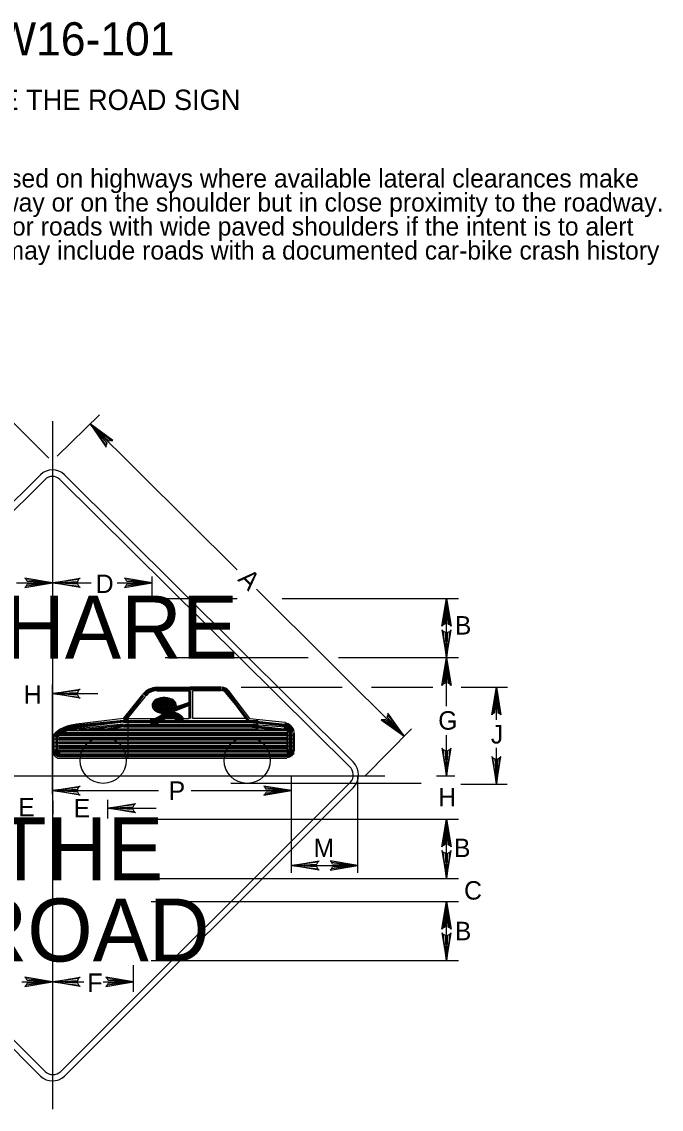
# Model space of a CAD drawing. Extents: x 0.012 to 0.188, y 0.004 to 0.259.
# Drawn here: x 0.1016 to 0.1882, y 0.112 to 0.2592 of the extents above; entities that cross this region are included whole.
import ezdxf

# ---------------------------------------------------------------- set-up
doc = ezdxf.new("R2010")
doc.units = 0
for name, color, linetype in [('1', 7, 'Continuous'), ('12', 7, 'Continuous'), ('2', 7, 'Continuous'), ('3', 7, 'Continuous')]:
    doc.layers.add(name, color=color, linetype=linetype)

# ---------------------------------------------------------------- blocks, each defined once
blk = doc.blocks.new('RARROW')
at = {"layer": '3'}
for p, q in [((-2.156, 0.28500000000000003), (-2.2665, 0.384625)), ((-2.2665, 0.384625), (0, 0)), ((0, 0), (-2.2665, -0.379125)), ((-2.156, 0.28500000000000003), (-2.075625, 0.12075)), ((0, 0), (-2.156, 0.28500000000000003)), ((-2.14975, -0.2705), (0, 0)), ((-2.075625, 0.12075), (0, 0)), ((0, 0), (-2.074, -0.108)), ((-2.2665, -0.379125), (-2.14975, -0.2705)), ((-2.074, -0.108), (-2.14975, -0.2705))]:
    blk.add_line(p, q, dxfattribs=at)

msp = doc.modelspace()

# ---------------------------------------------------------------- linework, layer by layer
at = {"layer": '1'}
for p, q in [((0.099875, 0.20550000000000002), (0.10525, 0.200125)), ((0.10575, 0.205125), (0.10575, 0.112)), ((0.106375, 0.200375), (0.112125, 0.20600000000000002)), ((0.110875, 0.20475000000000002), (0.13075, 0.185)), ((0.133375, 0.182375), (0.153375, 0.1625)), ((0.136875, 0.181125), (0.16075, 0.181125)), ((0.15912500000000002, 0.173125), (0.15912500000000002, 0.181125)), ((0.121, 0.173125), (0.140375, 0.173125)), ((0.1445, 0.173125), (0.16075, 0.173125)), ((0.15912500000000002, 0.16653560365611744), (0.15912500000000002, 0.173125)), ((0.13129158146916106, 0.16912213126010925), (0.14500189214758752, 0.16912213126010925)), ((0.14898049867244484, 0.16912213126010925), (0.15729158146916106, 0.16912213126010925)), ((0.161125, 0.169125), (0.167375, 0.169125)), ((0.165875, 0.16472308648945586), (0.165875, 0.169125)), ((0.148125, 0.15712500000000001), (0.154375, 0.1635)), ((0.1591348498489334, 0.15728102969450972), (0.1591348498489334, 0.1626118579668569)), ((0.165875, 0.156), (0.165875, 0.16091147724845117)), ((0.06075, 0.15712500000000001), (0.15075, 0.15712500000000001)), ((0.12991658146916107, 0.15612213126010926), (0.15570406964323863, 0.15612213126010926)), ((0.147125, 0.14400000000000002), (0.147125, 0.15712500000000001)), ((0.15775, 0.15712500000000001), (0.16025, 0.15712500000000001)), ((0.15916658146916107, 0.15712213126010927), (0.15916658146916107, 0.15712213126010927)), ((0.16105566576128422, 0.15602134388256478), (0.16733199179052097, 0.15602134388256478)), ((0.115625, 0.15125), (0.16075, 0.15125)), ((0.15912500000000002, 0.14325000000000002), (0.15912500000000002, 0.15125)), ((0.15916658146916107, 0.15124713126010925), (0.15916658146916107, 0.15124713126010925)), ((0.138125, 0.145), (0.147125, 0.145)), ((0.115625, 0.14325000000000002), (0.16075, 0.14325000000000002)), ((0.11912500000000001, 0.140125), (0.16075, 0.140125)), ((0.15912500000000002, 0.132125), (0.15912500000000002, 0.140125)), ((0.11912500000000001, 0.132125), (0.16075, 0.132125))]:
    msp.add_line(p, q, dxfattribs=at)
at = {"layer": '12'}
for p, q in [((0.065, 0.159), (0.104125, 0.197875)), ((0.065625, 0.15837500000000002), (0.10475, 0.19725)), ((0.10675, 0.19725), (0.146, 0.15837500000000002)), ((0.107375, 0.197875), (0.1465, 0.159)), ((0.11925000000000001, 0.1815), (0.11925000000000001, 0.184125)), ((0.100875, 0.18325), (0.10575, 0.18325)), ((0.10575, 0.18325), (0.111, 0.18325)), ((0.1145, 0.18325), (0.11925000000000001, 0.18325)), ((0.121, 0.181125), (0.13075, 0.181125)), ((0.10575, 0.154625), (0.10575, 0.1695)), ((0.10575, 0.16825), (0.11191756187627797, 0.16825)), ((0.115375, 0.164875), (0.11800000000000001, 0.168125)), ((0.115375, 0.164625), (0.11812500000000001, 0.168)), ((0.115625, 0.164625), (0.11812500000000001, 0.168)), ((0.115625, 0.1645), (0.11837500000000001, 0.167875)), ((0.115625, 0.1645), (0.11837500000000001, 0.167875)), ((0.115875, 0.164875), (0.11837500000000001, 0.167875)), ((0.11987500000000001, 0.169125), (0.124375, 0.169125)), ((0.11987500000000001, 0.169), (0.124375, 0.169)), ((0.11987500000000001, 0.168875), (0.124375, 0.168875)), ((0.11987500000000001, 0.16875), (0.124375, 0.16875)), ((0.11987500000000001, 0.168625), (0.12425, 0.168625)), ((0.12425, 0.164875), (0.12425, 0.168625)), ((0.128625, 0.169125), (0.124375, 0.169125)), ((0.128625, 0.169), (0.124375, 0.169)), ((0.128625, 0.168875), (0.124375, 0.168875)), ((0.128625, 0.16875), (0.124375, 0.16875)), ((0.124375, 0.164875), (0.124375, 0.168625)), ((0.1245, 0.164875), (0.1245, 0.168625)), ((0.1245, 0.164875), (0.1245, 0.168625)), ((0.128625, 0.168625), (0.12475, 0.168625)), ((0.12475, 0.164875), (0.12475, 0.168625)), ((0.132125, 0.164875), (0.12925, 0.168375)), ((0.132375, 0.164625), (0.129375, 0.1685)), ((0.13225, 0.1645), (0.129375, 0.168375)), ((0.132375, 0.164625), (0.1295, 0.1685)), ((0.1325, 0.164875), (0.129625, 0.168625)), ((0.124375, 0.167), (0.1205, 0.165625)), ((0.124125, 0.167), (0.1205, 0.16575)), ((0.1205, 0.166375), (0.1225, 0.167)), ((0.1205, 0.16625), (0.1225, 0.166875)), ((0.1205, 0.166125), (0.1225, 0.16675)), ((0.120625, 0.166125), (0.122375, 0.166625)), ((0.12075, 0.166), (0.12425, 0.167)), ((0.12425, 0.166875), (0.12125, 0.16575)), ((0.12425, 0.16675), (0.1215, 0.16575)), ((0.12425, 0.166625), (0.122, 0.16575)), ((0.12425, 0.167), (0.12425, 0.166625)), ((0.115375, 0.164875), (0.109, 0.164125)), ((0.115375, 0.164875), (0.115375, 0.164875)), ((0.115875, 0.164875), (0.12425, 0.164875)), ((0.116, 0.1595), (0.116, 0.164875)), ((0.132125, 0.164875), (0.12475, 0.164875)), ((0.1325, 0.164875), (0.1325, 0.164875)), ((0.1325, 0.164875), (0.13725, 0.164375)), ((0.115375, 0.164625), (0.109, 0.164)), ((0.115375, 0.1645), (0.109, 0.163875)), ((0.115375, 0.164375), (0.109, 0.16375)), ((0.115375, 0.164375), (0.109, 0.163625)), ((0.115375, 0.164125), (0.109, 0.1635)), ((0.109375, 0.1635), (0.133625, 0.1635)), ((0.1095, 0.164125), (0.1095, 0.164125)), ((0.115375, 0.164), (0.11075, 0.1635)), ((0.115375, 0.164), (0.111875, 0.1635)), ((0.115375, 0.163875), (0.11325, 0.1635)), ((0.115375, 0.16375), (0.114, 0.1635)), ((0.115375, 0.164625), (0.133625, 0.164625)), ((0.115375, 0.1645), (0.133625, 0.1645)), ((0.115375, 0.164375), (0.133625, 0.164375)), ((0.115375, 0.164375), (0.133625, 0.164375)), ((0.115375, 0.164), (0.133625, 0.164)), ((0.115375, 0.163875), (0.133625, 0.163875)), ((0.115375, 0.163875), (0.133625, 0.163875)), ((0.115375, 0.16375), (0.133625, 0.16375)), ((0.1155, 0.164125), (0.133625, 0.164125)), ((0.132375, 0.164), (0.137, 0.163375)), ((0.132375, 0.163875), (0.137, 0.163375)), ((0.132375, 0.16375), (0.137, 0.16325)), ((0.1325, 0.164625), (0.13725, 0.164125)), ((0.1325, 0.1645), (0.13725, 0.164)), ((0.1325, 0.164375), (0.13725, 0.163875)), ((0.1325, 0.164375), (0.13725, 0.163875)), ((0.1325, 0.164125), (0.13725, 0.16375)), ((0.1325, 0.164), (0.137125, 0.1635)), ((0.10575, 0.162625), (0.1385, 0.162625)), ((0.10575, 0.1605), (0.10575, 0.162625)), ((0.10575, 0.162125), (0.1385, 0.162125)), ((0.105875, 0.1605), (0.105875, 0.162625)), ((0.106, 0.1605), (0.106, 0.162625)), ((0.106, 0.1605), (0.106, 0.162625)), ((0.10625, 0.1605), (0.10625, 0.162625)), ((0.106375, 0.1605), (0.106375, 0.162625)), ((0.1065, 0.1605), (0.1065, 0.162625)), ((0.1065, 0.1605), (0.1065, 0.162625)), ((0.106625, 0.162875), (0.1375, 0.162875)), ((0.106625, 0.162875), (0.1375, 0.162875)), ((0.106625, 0.16275), (0.1375, 0.16275)), ((0.106625, 0.162625), (0.1375, 0.162625)), ((0.106625, 0.162375), (0.1375, 0.162375)), ((0.106625, 0.162375), (0.1375, 0.162375)), ((0.106625, 0.16225), (0.1375, 0.16225)), ((0.106625, 0.162125), (0.1375, 0.162125)), ((0.106625, 0.162), (0.1375, 0.162)), ((0.106625, 0.162), (0.1375, 0.162)), ((0.107, 0.163), (0.1375, 0.163)), ((0.107125, 0.16325), (0.1375, 0.16325)), ((0.10825, 0.163375), (0.1375, 0.163375)), ((0.108625, 0.163375), (0.1375, 0.163375)), ((0.1375, 0.163), (0.1375, 0.1605)), ((0.137625, 0.163), (0.137625, 0.1605)), ((0.137625, 0.163), (0.137625, 0.1605)), ((0.137875, 0.163), (0.137875, 0.1605)), ((0.138, 0.163), (0.138, 0.1605)), ((0.138125, 0.163), (0.138125, 0.1605)), ((0.138125, 0.163), (0.138125, 0.1605)), ((0.138375, 0.163), (0.138375, 0.1605)), ((0.1385, 0.163), (0.1385, 0.1605)), ((0.10575, 0.161625), (0.1385, 0.161625)), ((0.10575, 0.161125), (0.1385, 0.161125)), ((0.10575, 0.160625), (0.1385, 0.160625)), ((0.106625, 0.16175), (0.1375, 0.16175)), ((0.106625, 0.161625), (0.1375, 0.161625)), ((0.106625, 0.1615), (0.1375, 0.1615)), ((0.106625, 0.1615), (0.1375, 0.1615)), ((0.106625, 0.16125), (0.1375, 0.16125)), ((0.106625, 0.161125), (0.1375, 0.161125)), ((0.106625, 0.161), (0.1375, 0.161)), ((0.106625, 0.161), (0.1375, 0.161)), ((0.106625, 0.160875), (0.1375, 0.160875)), ((0.106625, 0.160625), (0.1375, 0.160625)), ((0.106625, 0.1605), (0.1375, 0.1605)), ((0.106625, 0.1605), (0.1375, 0.1605)), ((0.10575, 0.160125), (0.1385, 0.160125)), ((0.106625, 0.160375), (0.1375, 0.160375)), ((0.106625, 0.160125), (0.1375, 0.160125)), ((0.106625, 0.16), (0.1375, 0.16)), ((0.106625, 0.16), (0.1375, 0.16)), ((0.106625, 0.15987500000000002), (0.1375, 0.15987500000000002)), ((0.106625, 0.15975), (0.1375, 0.15975)), ((0.106625, 0.1595), (0.1375, 0.1595)), ((0.106875, 0.1595), (0.13725, 0.1595)), ((0.113, 0.1595), (0.113, 0.1595)), ((0.10475, 0.117125), (0.065625, 0.156125)), ((0.146125, 0.15625), (0.106875, 0.117125)), ((0.138125, 0.14400000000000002), (0.138125, 0.15712500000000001)), ((0.104125, 0.1165), (0.065, 0.1555)), ((0.10575, 0.155125), (0.1201182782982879, 0.155125)), ((0.1465, 0.1555), (0.107375, 0.1165)), ((0.12456088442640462, 0.155125), (0.138125, 0.155125)), ((0.10579158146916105, 0.15373556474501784), (0.10579158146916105, 0.15188725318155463)), ((0.11325, 0.151375), (0.11325, 0.153875)), ((0.11325, 0.15275), (0.11979435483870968, 0.15275)), ((0.11675, 0.12787500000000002), (0.11675, 0.1315)), ((0.10162500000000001, 0.12925), (0.10575, 0.12925)), ((0.10575, 0.12925), (0.11, 0.12925)), ((0.112625, 0.12925), (0.11675, 0.12925))]:
    msp.add_line(p, q, dxfattribs=at)
for centre in [(0.11263112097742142, 0.15923203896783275), (0.1321283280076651, 0.15923203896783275)]:
    msp.add_circle(centre, 0.0031246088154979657, dxfattribs=at)
for centre, radius, start, end in [((0.10574999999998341, 0.19625000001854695), 0.0022980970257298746, 45, 135), ((0.1057499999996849, 0.19624999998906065), 0.0014142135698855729, 45, 135), ((0.1199205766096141, 0.16670678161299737), 0.0023998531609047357, 90, 142.46745), ((0.1199205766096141, 0.16670678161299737), 0.002279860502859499, 90, 142.46745), ((0.1199205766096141, 0.16670678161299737), 0.002159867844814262, 90, 142.46745), ((0.1199205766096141, 0.16670678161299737), 0.002039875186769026, 90, 142.46745), ((0.1199205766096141, 0.16670678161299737), 0.0019496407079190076, 90, 142.46745), ((0.12866517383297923, 0.16792870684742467), 0.0007278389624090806, 37.53137777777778, 90), ((0.12867957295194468, 0.16790670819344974), 0.0011999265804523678, 37.53137777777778, 90), ((0.12867957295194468, 0.16790670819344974), 0.001079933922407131, 37.53137777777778, 90), ((0.12867957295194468, 0.16790670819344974), 0.0009599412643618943, 37.53137777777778, 90), ((0.12867957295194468, 0.16790670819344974), 0.0008399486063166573, 37.53137777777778, 90), ((0.11889765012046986, 0.16722611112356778), 0.0024427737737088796, 272.29644444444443, 318.79271944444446), ((0.11889765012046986, 0.16722611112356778), 0.0025627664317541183, 272.29644444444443, 318.79271944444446), ((0.11889765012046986, 0.16722611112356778), 0.0026827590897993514, 272.29644444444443, 318.79271944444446), ((0.11889765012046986, 0.16722611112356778), 0.0028027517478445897, 272.29644444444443, 318.79271944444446), ((0.11889765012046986, 0.16722611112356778), 0.0029227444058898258, 272.29644444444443, 318.79271944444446), ((0.11889765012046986, 0.16722611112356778), 0.003042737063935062, 272.29644444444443, 318.79271944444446), ((0.11889765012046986, 0.16722611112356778), 0.003162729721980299, 272.29644444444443, 318.79271944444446), ((0.12165017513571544, 0.16339083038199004), 0.0024066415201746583, 35.41012500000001, 112.33950555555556), ((0.12165017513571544, 0.16339083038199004), 0.0022866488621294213, 35.41012500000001, 112.33950555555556), ((0.12165017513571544, 0.16339083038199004), 0.0021666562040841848, 35.41012500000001, 112.33950555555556), ((0.12165017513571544, 0.16339083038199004), 0.002046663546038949, 35.41012500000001, 112.33950555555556), ((0.12165017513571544, 0.16339083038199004), 0.0019266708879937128, 35.41012500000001, 112.33950555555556), ((0.12165017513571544, 0.16339083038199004), 0.0018066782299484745, 35.41012500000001, 112.33950555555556), ((0.12165017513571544, 0.16339083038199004), 0.0016866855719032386, 35.41012500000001, 112.33950555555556), ((0.12165017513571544, 0.16339083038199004), 0.0015666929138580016, 35.41012500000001, 112.33950555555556), ((0.13703152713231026, 0.16280642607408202), 0.0006616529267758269, 11.546911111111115, 82.31175555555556), ((0.13703152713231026, 0.16280642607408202), 0.0007816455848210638, 11.546911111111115, 82.31175555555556), ((0.13703152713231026, 0.16280642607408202), 0.0009016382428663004, 11.546911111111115, 82.31175555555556), ((0.13703152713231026, 0.16280642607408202), 0.0010216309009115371, 11.546911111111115, 82.31175555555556), ((0.13703152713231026, 0.16280642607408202), 0.0011416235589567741, 11.546911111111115, 82.31175555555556), ((0.13703152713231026, 0.16280642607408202), 0.001261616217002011, 11.546911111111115, 82.31175555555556), ((0.13703152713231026, 0.16280642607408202), 0.0013816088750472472, 11.546911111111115, 82.31175555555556), ((0.13703152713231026, 0.16280642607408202), 0.0015016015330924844, 11.546911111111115, 82.31175555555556), ((0.10674439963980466, 0.16043749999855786), 0.0009395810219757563, 176.185925, 266.185925), ((0.10677353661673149, 0.1605671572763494), 0.0008399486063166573, 180, 270), ((0.10677353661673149, 0.1605671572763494), 0.0007199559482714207, 180, 270), ((0.10677353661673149, 0.1605671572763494), 0.0005999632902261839, 180, 270), ((0.10677353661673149, 0.1605671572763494), 0.00047997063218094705, 180, 270), ((0.10677353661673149, 0.1605671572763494), 0.00035997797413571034, 180, 270), ((0.10677353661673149, 0.1605671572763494), 0.00023998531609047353, 180, 270), ((0.10677353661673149, 0.1605671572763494), 0.00011999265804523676, 180, 270), ((0.137542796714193, 0.1605671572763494), 0.0009599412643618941, 270, 0), ((0.137542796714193, 0.1605671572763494), 0.0008399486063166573, 270, 0), ((0.137542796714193, 0.1605671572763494), 0.0007199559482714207, 270, 0), ((0.137542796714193, 0.1605671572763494), 0.0005999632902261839, 270, 0), ((0.137542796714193, 0.1605671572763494), 0.00047997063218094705, 270, 0), ((0.137542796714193, 0.1605671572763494), 0.00035997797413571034, 270, 0), ((0.137542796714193, 0.1605671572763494), 0.00023998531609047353, 270, 0), ((0.137542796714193, 0.1605671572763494), 0.00011999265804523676, 270, 0), ((0.14474999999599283, 0.15724999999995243), 0.0024748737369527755, 315, 45), ((0.144999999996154, 0.15725000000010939), 0.0015051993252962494, 318.3664611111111, 48.366461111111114), ((0.10575000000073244, 0.11812500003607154), 0.002298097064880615, 225, 315), ((0.10581249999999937, 0.11818750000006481), 0.0015026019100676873, 225, 315)]:
    msp.add_arc(centre, radius, start, end, dxfattribs=at)
for centre, major_axis, ratio, start_param, end_param in [((0.12089701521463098, 0.16664918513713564), (-0.0016503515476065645, 4.884683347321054e-05), 0.6562755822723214, 3.1209935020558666, 7.708520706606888), ((0.12089701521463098, 0.16664918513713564), (-0.001530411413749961, 4.529686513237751e-05), 0.6293374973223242, 3.1209935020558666, 7.708520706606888), ((0.12089701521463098, 0.16664918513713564), (-0.0014104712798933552, 4.174689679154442e-05), 0.5978180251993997, 3.1209935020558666, 7.708520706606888), ((0.12089701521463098, 0.16664918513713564), (-0.0012905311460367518, 3.81969284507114e-05), 0.5604398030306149, 3.1209935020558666, 7.708520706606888), ((0.12089701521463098, 0.16664918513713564), (-0.0011705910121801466, 3.464696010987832e-05), 0.5154019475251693, 3.1209935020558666, 7.708520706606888), ((0.12089701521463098, 0.16664918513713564), (-0.0010506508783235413, 3.109699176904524e-05), 0.46008123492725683, 3.1209935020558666, 7.708520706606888), ((0.12089701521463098, 0.16664918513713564), (-0.000930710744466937, 2.7547023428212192e-05), 0.3905022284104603, 3.1209935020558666, 7.708520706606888), ((0.12089701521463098, 0.16664918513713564), (-0.0008107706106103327, 2.399705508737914e-05), 0.30033709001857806, 3.1209935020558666, 7.708520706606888), ((0.12089701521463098, 0.16664918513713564), (-0.0006908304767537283, 2.044708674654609e-05), 0.17886349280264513, 3.1209935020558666, 7.708520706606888), ((0.12089701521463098, 0.16664918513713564), (-0.0005708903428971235, 1.6897118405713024e-05), 0.0063483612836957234, 3.1209935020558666, 7.708520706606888), ((0.12089701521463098, 0.16664918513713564), (-0.0012905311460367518, 3.81969284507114e-05), 0.5604398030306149, 2.348331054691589, 2.5781574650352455), ((0.10937570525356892, 0.16079443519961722), (-0.00424683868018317, 5.20087739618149e-19), 0.7829277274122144, 4.798996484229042, 5.706620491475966), ((0.10937875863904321, 0.16079443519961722), (-0.004126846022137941, 5.0539287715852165e-19), 0.7766161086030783, 4.798996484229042, 5.706620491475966), ((0.10938204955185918, 0.16079443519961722), (-0.004006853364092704, 4.906980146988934e-19), 0.7699264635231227, 4.798996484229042, 5.706620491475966), ((0.1093856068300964, 0.16079443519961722), (-0.003886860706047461, 4.760031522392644e-19), 0.7628237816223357, 4.798996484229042, 5.706620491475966), ((0.1093894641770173, 0.16079443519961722), (-0.0037668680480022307, 4.613082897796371e-19), 0.7552685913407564, 4.798996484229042, 5.706620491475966), ((0.1093936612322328, 0.16079443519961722), (-0.003646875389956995, 4.466134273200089e-19), 0.747216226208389, 4.798996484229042, 5.706620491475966)]:
    msp.add_ellipse(centre, major_axis=major_axis, ratio=ratio, start_param=start_param, end_param=end_param, dxfattribs=at)

# ---------------------------------------------------------------- block references
at = {"layer": '3'}
for p, xscale, yscale, rotation in [((0.110875, 0.20475000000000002), 0.0016545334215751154, -0.0016366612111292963, 134.13104221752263), ((0.10575, 0.18325), 0.0016545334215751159, 0.0016366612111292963, 180), ((0.15912500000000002, 0.181125), 0.0016545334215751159, 0.0016366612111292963, 90), ((0.15912500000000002, 0.173125), 0.0016545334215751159, -0.0016366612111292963, -90), ((0.15912500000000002, 0.173125), 0.0016545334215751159, 0.0016366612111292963, 90), ((0.10575, 0.16825), 0.0016545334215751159, 0.0016366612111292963, 180), ((0.165875, 0.169125), 0.0016545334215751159, 0.0016366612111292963, 90), ((0.153375, 0.1625), 0.0016545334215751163, -0.001636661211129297, -45.23651044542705), ((0.15912500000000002, 0.15712500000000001), 0.0016545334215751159, -0.0016366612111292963, -90), ((0.165875, 0.156), 0.0016545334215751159, -0.0016366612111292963, -90), ((0.10575, 0.155125), 0.0016545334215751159, 0.0016366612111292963, 180), ((0.11325, 0.15275), 0.0016545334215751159, 0.0016366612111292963, 180), ((0.15912500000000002, 0.15125), 0.0016545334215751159, 0.0016366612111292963, 90), ((0.15912500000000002, 0.14325000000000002), 0.0016545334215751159, -0.0016366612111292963, -90), ((0.138125, 0.145), 0.0016545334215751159, 0.0016366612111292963, 180), ((0.15912500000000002, 0.140125), 0.0016545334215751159, 0.0016366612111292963, 90), ((0.15912500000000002, 0.132125), 0.0016545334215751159, -0.0016366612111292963, -90), ((0.10575, 0.12925), 0.0016545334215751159, 0.0016366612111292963, 180)]:
    msp.add_blockref('RARROW', p, dxfattribs=dict(at, xscale=xscale, yscale=yscale, rotation=rotation))
at = {"layer": '3', "xscale": 0.0016545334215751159, "yscale": -0.0016366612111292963}
for p in [(0.10575, 0.18325), (0.11925000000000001, 0.18325), (0.138125, 0.155125), (0.147125, 0.145), (0.10575, 0.12925), (0.11675, 0.12925)]:
    msp.add_blockref('RARROW', p, dxfattribs=at)

# ---------------------------------------------------------------- texts
at = {"layer": '1'}
for s, height, p in [('W16-101', 0.0045000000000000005, (0.09786363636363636, 0.254625)), ('SHARE THE ROAD SIGN', 0.00275025, (0.0885, 0.24725)), ('B', 0.0024997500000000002, (0.16025, 0.17625)), ('G', 0.0024997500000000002, (0.158, 0.163375)), ('J', 0.0024997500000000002, (0.165125, 0.1615)), ('H', 0.0024997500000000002, (0.158, 0.153)), ('M', 0.0024997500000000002, (0.141125, 0.146125)), ('B', 0.0024997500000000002, (0.160125, 0.146125)), ('C', 0.0024997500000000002, (0.1615, 0.140375)), ('B', 0.0024997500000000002, (0.16025, 0.134875))]:
    msp.add_text(s, height=height, dxfattribs=at).set_placement(p)
at = {"layer": '12'}
for s, height, p in [('D', 0.0024997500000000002, (0.111625, 0.181875)), ('SHARE', 0.008517, (0.091625, 0.17300000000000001)), ('H', 0.0024997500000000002, (0.10187500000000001, 0.166875)), ('P', 0.0024997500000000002, (0.1215, 0.153875)), ('E', 0.0024997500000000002, (0.101125, 0.151625)), ('E', 0.0024997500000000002, (0.108625, 0.1515)), ('THE', 0.008517, (0.098, 0.14300000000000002)), ('ROAD', 0.008517, (0.094125, 0.132)), ('F', 0.0024997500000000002, (0.1105, 0.12787500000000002))]:
    msp.add_text(s, height=height, dxfattribs=at).set_placement(p)
msp.add_text('A', height=0.0024997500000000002, rotation=315, dxfattribs=at).set_placement((0.13075, 0.183625))
at = {"layer": '2'}
for s, p in [('     The Share the Road Sign (W16-101) may be used on highways where available lateral clearances make', (0.026125, 0.23674962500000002)), ('it likely that bicyclists will either travel on the roadway or on the shoulder but in close proximity to the roadway.', (0.026125, 0.233499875)), ('It may also be used in conjunction with bike lanes or roads with wide paved shoulders if the intent is to alert ', (0.026125, 0.230250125)), ('motorists to the presence of cyclists.  Other uses may include roads with a documented car-bike crash history', (0.026125, 0.227000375))]:
    msp.add_text(s, height=0.0024997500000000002, dxfattribs=at).set_placement(p)

doc.saveas('drawing.dxf')
